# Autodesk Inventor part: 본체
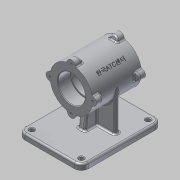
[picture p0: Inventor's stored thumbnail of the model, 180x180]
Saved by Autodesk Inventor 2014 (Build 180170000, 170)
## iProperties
Created: 2015-12
Part Number: 본체
Material: 알루미늄 6061
Document SubType Name: Modeling
Designer: L10
Density: 2.71 g/cm^3
Appearance: 알루미늄 - 평지
Mass: 1154.84 g
Surface Area: 823.447 cm^2
Volume: 426.142 cm^3
Author: L10
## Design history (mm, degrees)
sketch "스케치1"
  geometry: C1 r 37 at (0, 0); 1 further point
  constraints: 1 centre point, 1 coincident
  dimensions: "d0" = 74 diameter of C1
extrude "돌출1" new body sketch "스케치1" stored distance "d1" = 85; taper "d2" = 0 deg
sketch "스케치2"
  geometry: L1 (-42.5, -37)-(-42.5, 37) reference; L2 (-42.5, 37)-(42.5, 37) reference; L3 (42.5, 37)-(42.5, -37) reference; L4 (42.5, -37)-(-42.5, -37) reference; L5 (-42.5, 0)-(-20.5, 0); L6 (-20.5, 0)-(-20.5, 23.5); L7 (-20.5, 23.5)-(-42.5, 23.5); L8 (-42.5, 23.5)-(-42.5, 0); L9 (-20.5, 0)-(20.5, 0); L10 (20.5, 0)-(20.5, 21); L11 (20.5, 21)-(-20.5, 21); L12 (-20.5, 21)-(-20.5, 0); L13 (20.5, 0)-(42.5, 0); L14 (42.5, 0)-(42.5, 23.5); L15 (42.5, 23.5)-(20.5, 23.5); L16 (20.5, 23.5)-(20.5, 0); 2 further points
  constraints: 24 end point, 6 parallel, 3 horizontal, 3 perpendicular, 2 collinear, 1 coincident, 1 midpoint
  dimensions: "d3" = 47 diameter of L7 L9; "d4" = 42 diameter of L11 L9; "d5" = 22 distance of L6.end L7.end; "d6" = 41 distance of L10.end L11.end; "d7" = 85 distance between parallel lines of L14 L8 (derived)
revolve "회전1" sketch "스케치2" stored, may be unused: angle "d8" = 90 deg
node "작업 평면1"
sketch "스케치4"
  geometry: L1 (55, 60)-(-55, 60); L2 (-55, 60)-(-55, -80); L3 (-55, -80)-(55, -80); L4 (55, -80)-(55, 60); L5 (-37, -42.5)-(37, -42.5) reference; 4 further points
  constraints: 8 end point, 2 parallel, 1 horizontal, 1 midpoint, 1 perpendicular, 1 vertical alignment
  dimensions: "d13" = 140 distance of L3.end L1.start; "d14" = 110 distance of L1.start L1.end; "d15" = 37.5 distance between parallel lines of L5 L3
extrude "돌출3" join sketch "스케치4" distance "d16" = 10; taper "d17" = 0 deg
fillet "모깎기1" dims "d18" = 12
hole "구멍1" diameter "d21" = 8; stored, may be unused: countersink angle "d25" = 90 deg, drill point angle "d27" = 118 deg; dims "d19" = 10, "d20" = 10, "d22" = 6, "d23" = 4, "d24" = 2, "d26" = 8
hole "구멍2" diameter "d30" = 8; stored, may be unused: countersink angle "d34" = 90 deg, drill point angle "d36" = 118 deg; dims "d28" = 10, "d29" = 10, "d31" = 6, "d32" = 4, "d33" = 2, "d35" = 8
hole "구멍3" diameter "d39" = 8; stored, may be unused: countersink angle "d43" = 90 deg, drill point angle "d45" = 118 deg; dims "d37" = 10, "d38" = 10, "d40" = 6, "d41" = 4, "d42" = 2, "d44" = 8
hole "구멍4" diameter "d48" = 8; stored, may be unused: countersink angle "d52" = 90 deg, drill point angle "d54" = 118 deg; dims "d46" = 10, "d47" = 10, "d49" = 6, "d50" = 4, "d51" = 2, "d53" = 8
sketch "스케치6"
  geometry: L1 (-55, 48)-(-55, -68) reference; L2 (-43, -80)-(43, -80) reference; L3 (-6, -25)-(6, -25); L4 (6, -25)-(6, 25); L5 (6, 25)-(-6, 25); L6 (-6, 25)-(-6, -25); L7 (-37, -4)-(37, -4); L8 (37, -4)-(37, 4); L9 (37, 4)-(-37, 4); L10 (-37, 4)-(-37, -4); 3 further points
  constraints: 16 end point, 4 parallel, 2 horizontal, 2 midpoint, 2 perpendicular, 1 horizontal alignment, 1 vertical alignment
  dimensions: "d59" = 12 distance of L4.end L5.end; "d60" = 8 distance of L9.end L7.start; "d61" = 76 distance between parallel lines of L2 L7; "d62" = 49 distance between parallel lines of L1 L6; "d63" = 50 distance of L3.end L4.end; "d64" = 74 distance of L8.end L9.end
extrude "돌출4" join sketch "스케치6" stored distance "d65" = 10; taper "d66" = 0 deg
fillet "모깎기2" dims "d67" = 3
chamfer "모따기1" distance "d71" = 1; stored, may be unused: second distance "d72" = 2, angle "d73" = 20 deg
chamfer "모따기2" distance "d74" = 1; stored, may be unused: second distance "d75" = 2, angle "d76" = 20 deg
fillet "모깎기6" dims "d77" = 0.3
feature "면 기울기1" dims angle "d78" = 7 deg
feature "면 기울기2" dims angle "d79" = 7 deg
fillet "모깎기7" dims "d80" = 3
fillet "모깎기8" dims "d81" = 3
fillet "모깎기9" dims "d82" = 3
sketch "스케치9"
  geometry: L1 (-42.5, 31.009)-(-42.5, 44); L2 (-42.5, 44)-(-32.229, 44); L3 (-32.229, 44)-(-27.5, 31.009); L4 (-27.5, 31.009)-(-42.5, 31.009); L5 (-42.5, 37)-(-42.5, -37) reference; L6 (-42.5, 37)-(42.5, 37) reference; 1 further point
  constraints: 8 end point, 1 parallel, 1 perpendicular, 1 point on line, 1 vertical
  dimensions: "d92" = 15 distance of L3.end L1.start; "d93" = 7 distance of L5.start L1.end; "d94" = 110 deg angle of L3 L6; "d95" = 12.99148 distance of L1.start L1.end
extrude "돌출6" join sketch "스케치9" stored distance "d96" = 14; taper "d97" = 0 deg
fillet "모깎기10" dims "d98" = 7
fillet "모깎기11" dims "d99" = 3
hole "구멍5" diameter "d102" = 3.242; stored, may be unused: countersink angle "d106" = 90 deg, drill point angle "d108" = 118 deg; dims "d103" = 9, "d104" = 4, "d105" = 2, "d107" = 11, "d118" = 10, "d119" = 10
sketch "스케치12"
  geometry: L1 (0, 0)-(-26.163, 26.163); L2 (80.055, 0)-(-95.329, 0) reference; A1 r 37 centre (0, 0) between (-9.104, 35.863) and (-35.863, 9.104) reference
  constraints: 2 end point, 1 point on circle
  dimensions: "d120" = 45 deg angle of L1 L2
node "작업 평면3"
sketch "스케치13"
  geometry: L1 (-26.604, 3.602)-(26.604, 3.602); L2 (26.604, 3.602)-(26.604, -3.602); L3 (26.604, -3.602)-(-26.604, -3.602); L4 (-26.604, -3.602)-(-26.604, 3.602); 3 further points
  constraints: 2 midpoint, 1 horizontal alignment, 1 vertical alignment, 2 other
  dimensions: "d121" = 53.2089 distance of L1.start L1.end; "d122" = 7.20489 distance of L1.end L2.end; "d123" = 26.60445 horizontal distance of point (0, 3.602) point (26.604, 0)
feature "엠보싱2" sketch "스케치13" dims "d124" = 0.5, "d125" = 0
node "솔리드1"
pattern_circular "원형 패턴1" dims "d110" = 360 deg
mirror "대칭1"
node "절단 모서리 투영1"
